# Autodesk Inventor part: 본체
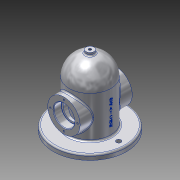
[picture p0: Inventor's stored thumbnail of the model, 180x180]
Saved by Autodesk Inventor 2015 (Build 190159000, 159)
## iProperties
Created: 2019-11
Part Number: 본체
Material: 알루미늄 6061
Document SubType Name: Modeling
Designer: Lineart
Density: 2.7 g/cm^3
Appearance: 알루미늄 - 평지
Mass: 1106.12 g
Surface Area: 883.263 cm^2
Volume: 409.676 cm^3
Author: Lineart
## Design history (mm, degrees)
sketch "스케치1"
  geometry: C1 r 70 at (0, 0); 1 further point
  constraints: 1 centre point, 1 coincident
  dimensions: "d0" = 140 diameter of C1
extrude "돌출1" new body sketch "스케치1" distance "d1" = 10; taper "d2" = 0 deg
sketch "스케치2"
  geometry: C1 r 70 at (0, 0) reference; C2 r 40 at (0, 0); 1 further point
  constraints: 1 centre point, 1 coincident
  dimensions: "d3" = 80 diameter of C2
extrude "돌출2" join sketch "스케치2" distance "d4" = 80; taper "d5" = 0 deg
sketch "스케치3"
  geometry: L1 (40, 90)-(-40, 90) reference; L2 (-40, 10)-(40, 10) reference; L3 (70, 10)-(-70, 10) reference; L4 (-70, 0)-(70, 0) reference; L5 (0, 90)-(40, 90); L6 (40, 90)-(-40, 90) reference; L7 (0, 90)-(0, 130); A1 r 40 centre (0, 90) between (40, 90) and (0, 130); 1 further point
  constraints: 4 end point, 2 point on circle, 1 centre point, 1 collinear, 1 midpoint, 1 perpendicular
  dimensions: "d6" = 80 diameter of A1 (derived)
revolve "회전1" sketch "스케치3" stored, may be unused: angle "d7" = 90 deg
node "작업 평면1"
sketch "스케치4"
  geometry: C1 r 40 at (0, 0) reference; C2 r 40 at (0, 0) reference; C3 r 70 at (0, 0) reference; C4 r 7.5 at (0, 0); 1 further point
  constraints: 1 centre point, 1 coincident
  dimensions: "d9" = 15 diameter of C4
extrude "돌출3" join sketch "스케치4" distance "d10" = 50; taper "d11" = 0 deg
sketch "스케치5"
  geometry: L1 (-70, 0)-(70, 0) reference; C1 r 31 at (0, 50); 2 further points
  constraints: 1 centre point, 1 midpoint, 1 vertical alignment
  dimensions: "d12" = 62 diameter of C1; "d13" = 50 distance from line of L1 C1.centre
extrude "돌출4" join sketch "스케치5" stored distance "d14" = 100; taper "d15" = 0 deg
sketch "스케치6"
  geometry: C1 r 40 at (0, 0) reference; C2 r 70 at (0, 0) reference; C3 r 30 at (0, 0); 1 further point
  constraints: 1 centre point, 1 coincident
  dimensions: "d16" = 60 diameter of C3
extrude "돌출5" cut sketch "스케치6" distance "d17" = 90; taper "d18" = 0 deg
sketch "스케치7"
  geometry: L1 (30, 90)-(-30, 90) reference; L2 (30, 0)-(-30, 0) reference; L3 (0, 120)-(0, 90); L4 (0, 90)-(30, 90); L5 (40, 90)-(-40, 90) reference; A1 r 30 centre (0, 90) between (30, 90) and (0, 120); 1 further point
  constraints: 4 end point, 2 point on circle, 1 centre point, 1 collinear, 1 midpoint, 1 vertical
  dimensions: "d19" = 60 diameter of A1 (derived)
revolve "회전2" sketch "스케치7" stored, may be unused: angle "d20" = 90 deg
sketch "스케치8"
  geometry: C1 r 31 at (0, 0) reference; C2 r 20 at (0, 0); 1 further point
  constraints: 1 centre point, 1 coincident
  dimensions: "d21" = 40 diameter of C2
extrude "돌출6" cut sketch "스케치8" distance "d22" = 15; taper "d23" = 0 deg
sketch "스케치9"
  geometry: C1 r 20 at (0, 0) reference; C2 r 20 at (0, 0) reference; C3 r 16.5 at (0, 0); 1 further point
  constraints: 1 centre point, 1 coincident
  dimensions: "d24" = 33 diameter of C3
extrude "돌출7" cut sketch "스케치9" distance "d25" = 30; taper "d26" = 0 deg
sketch "스케치10"
  geometry: C1 r 20 at (0, 0) reference; C2 r 31 at (0, 0) reference; 2 further points
  constraints: 1 vertical alignment
  dimensions: "d27" = 26 distance of C1.centre point (0, 26)
hole "구멍1" sketch "스케치10" at (0, 26) diameter "d28" = 3.242; stored, may be unused: countersink angle "d32" = 90 deg, drill point angle "d34" = 118 deg; dims "d29" = 8, "d30" = 4, "d31" = 2, "d33" = 10
sketch "스케치11"
  geometry: C1 r 7.5 at (0, 0) reference; 2 further points
  constraints: 1 coincident
hole "구멍2" sketch "스케치11" at (0, 0) diameter "d38" = 5.188; stored, may be unused: countersink angle "d42" = 90 deg, drill point angle "d44" = 0 deg; dims "d39" = 12, "d40" = 4, "d41" = 2, "d43" = 30
sketch "스케치12"
  geometry: C1 r 40 at (0, 0) reference; C2 r 70 at (0, 0) reference; 3 further points
  constraints: 2 horizontal alignment
  dimensions: "d54" = 55 distance of point (0, 0) point (-55, 0); "d55" = 55 distance of point (55, 0) point (0, 0)
hole "구멍3" sketch "스케치12" at (55, 0), (-55, 0) diameter "d47" = 9; stored, may be unused: countersink angle "d51" = 90 deg, drill point angle "d53" = 0 deg; dims "d48" = 12, "d49" = 4, "d50" = 2, "d52" = 30
fillet "모깎기1" dims "d56" = 3
fillet "모깎기2" dims "d57" = 0.3
chamfer "모따기1" distance "d58" = 1; stored, may be unused: second distance "d59" = 2, angle "d60" = 45 deg
node "작업 평면2"
sketch "스케치14"
  geometry: L1 (-10, 70)-(-10, -70) reference; 3 further points
  constraints: 1 horizontal alignment, 1 midpoint, 1 other
  dimensions: "d61" = 50 distance from line of L1 point (40, 0)
feature "엠보싱1" sketch "스케치14" dims "d1" = 10, "d2" = 0, "d7" = 90 deg, "d62" = 0.5, "d63" = 0
node "솔리드1"
mirror "대칭1"
pattern_circular "원형 패턴1" dims angle "d36" = 360 deg
mirror "대칭2"
node "투영된 루프1"
node "투영된 루프2"
node "투영된 루프3"
node "투영된 루프4"
node "투영된 루프5"
node "투영된 루프6"
node "투영된 루프7"
node "투영된 루프8"
node "투영된 루프9"
node "투영된 루프10"
node "투영된 루프11"
node "투영된 루프12"
other parameters: "d8" = -135
